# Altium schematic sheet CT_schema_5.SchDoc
size 383 x 218 mm
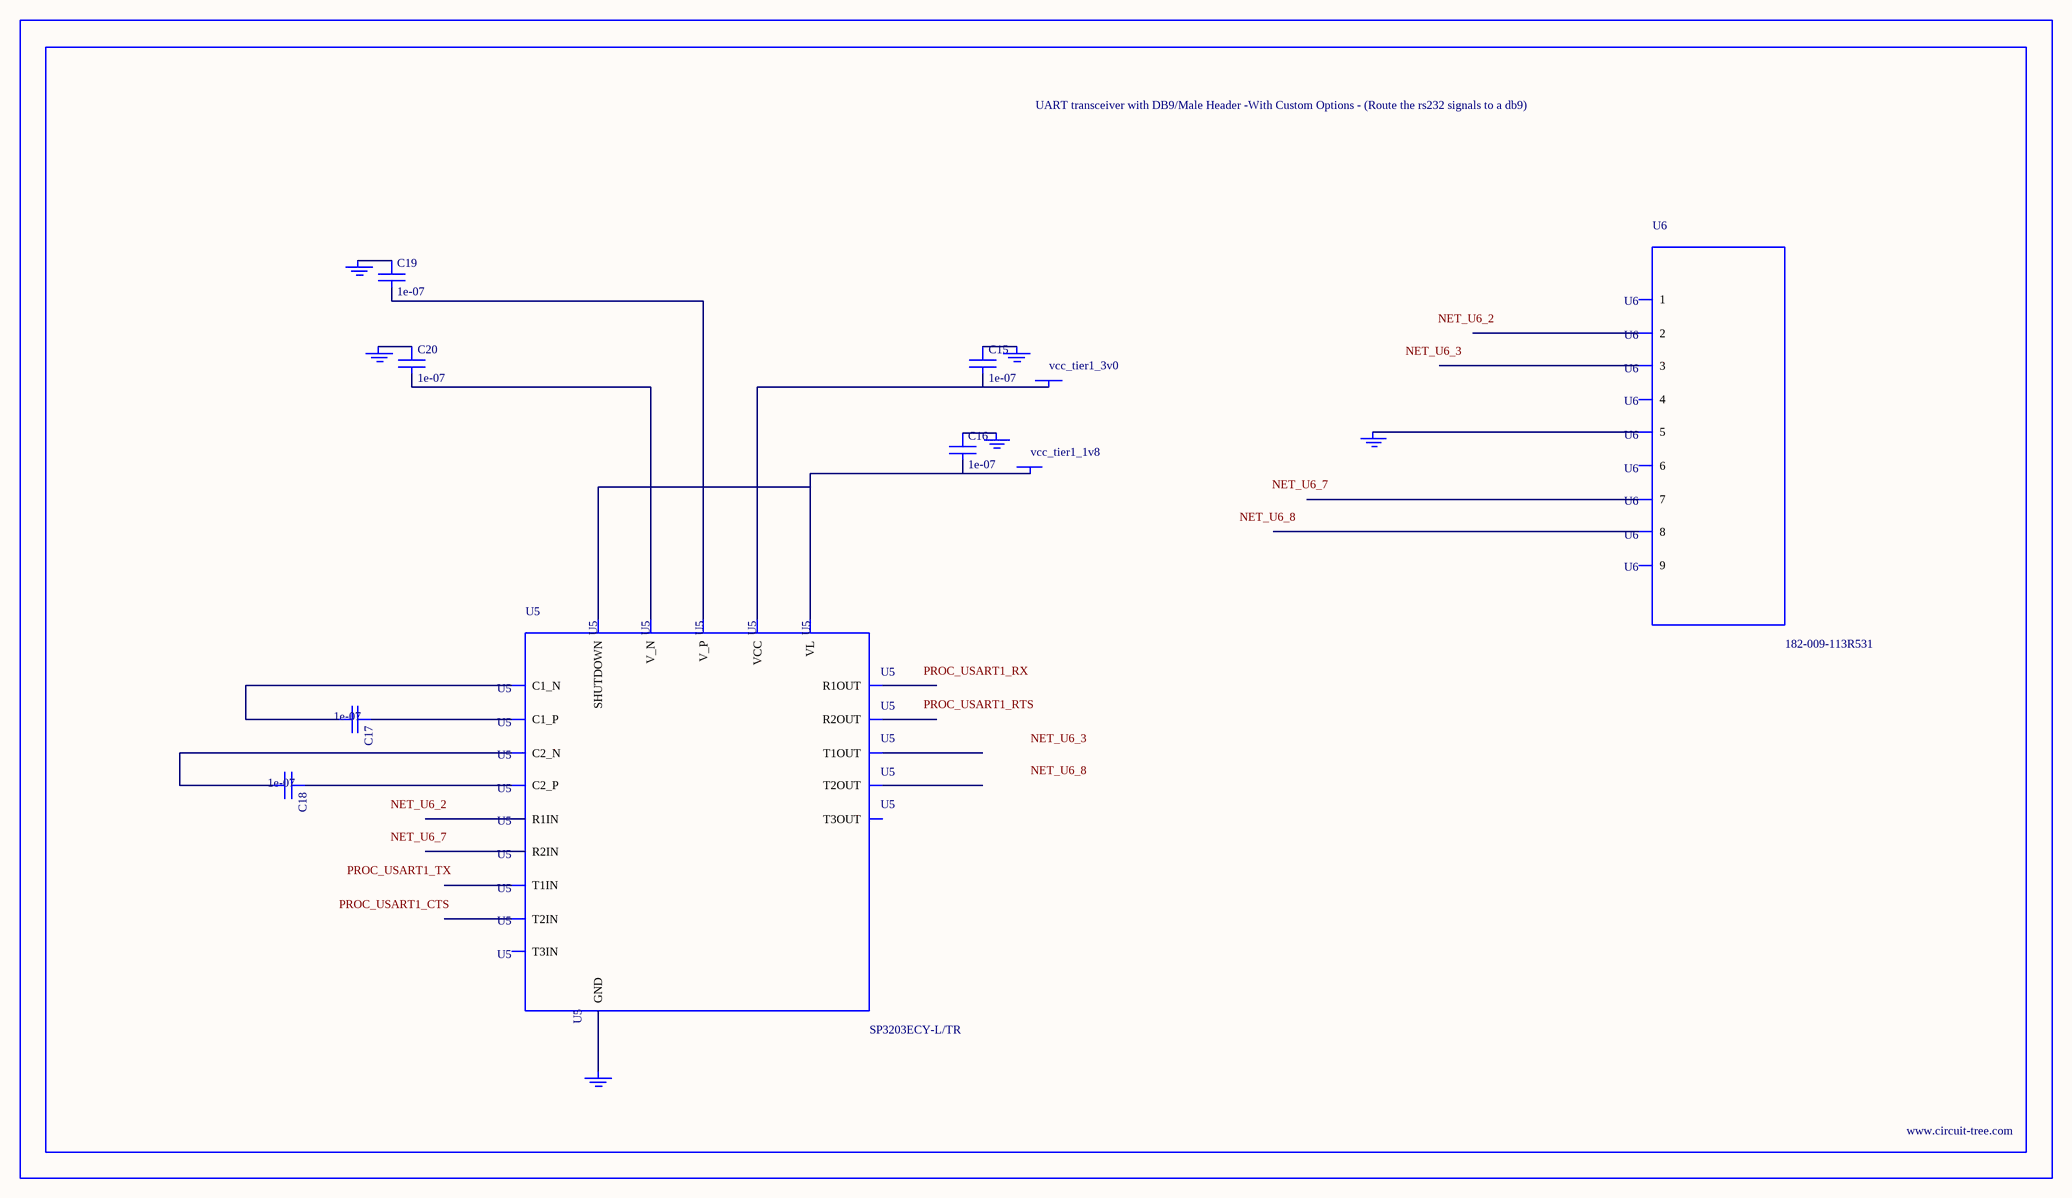
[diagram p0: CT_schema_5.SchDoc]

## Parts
BORDER4  (no value)
C15  1e-07  [C0402]
C16  1e-07  [C0402]
C17  1e-07  [C0402]
C18  1e-07  [C0402]
C19  1e-07  [C0402]
C20  1e-07  [C0402]
GND_INSTANCE_4_0  (no value)
GND_INSTANCE_4_1  (no value)
GND_INSTANCE_4_2  (no value)
GND_INSTANCE_4_3  (no value)
GND_INSTANCE_4_4  (no value)
GND_INSTANCE_4_5  (no value)
POWER_INSTANCE_4_0  vcc_tier1_1v8
POWER_INSTANCE_4_1  vcc_tier1_3v0
U5  SP3203ECY-L/TR  [TSSOP20-I]
U6  182-009-113R531  [182-009-MALE]

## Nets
NetC15_1: C15.1 GND_INSTANCE_4_3.0(GND)
NetC15_2: C15.2 POWER_INSTANCE_4_1.0(PWR) U5.19(VCC)
NetC16_1: C16.1 GND_INSTANCE_4_2.0(GND)
NetC16_2: C16.2 POWER_INSTANCE_4_0.0(PWR) U5.12(VL) U5.20(SHUTDOWN)
NetC17_1: C17.1 U5.1(C1_P)
NetC17_2: C17.2 U5.3(C1_N)
NetC18_1: C18.1 U5.4(C2_P)
NetC18_2: C18.2 U5.5(C2_N)
NetC19_1: C19.1 GND_INSTANCE_4_0.0(GND)
NetC19_2: C19.2 U5.2(V_P)
NetC20_1: C20.1 GND_INSTANCE_4_1.0(GND)
NetC20_2: C20.2 U5.6(V_N)
NetGND_INSTANCE_4_4_0: GND_INSTANCE_4_4.0(GND) U5.18(GND)
NetGND_INSTANCE_4_5_0: GND_INSTANCE_4_5.0(GND) U6.5

Not connected (* = marked no-connect by the designer): U5 7(T1IN) 8(T2IN) 9(T3IN) 10(R2OUT) 11(R1OUT) 13(R2IN) 14(R1IN) 15(T3OUT) 16(T2OUT) 17(T1OUT); U6 1 2 3 4 6 7 8 9

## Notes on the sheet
- Labels drawn without touching a wire or pin: NET_U6_2, NET_U6_3, NET_U6_7, NET_U6_8, PROC_USART1_CTS, PROC_USART1_RTS, PROC_USART1_RX, PROC_USART1_TX

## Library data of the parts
BORDER4 = BORDER_PAGE4
C15-C20 = C0402C104K3RACTU
GND_INSTANCE_4_0-GND_INSTANCE_4_5 = GND
POWER_INSTANCE_4_0 POWER_INSTANCE_4_1 = PWR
